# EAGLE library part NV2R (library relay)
MOTORUMPOL RELAIS 12V Ningbo Forward Relay Corporation LTD. Ningbo.Huaguan Electronics Corporation LTD. Source: http://www.dblectro.com/site/pdf/NV2R.pdf http://www2.produktinfo.conrad.com/datenblaetter/500000-524999/505013-da-01-de-Motorumpolrelais_12V.pdf Elli-Echo ER20T-S-DC12V - 20A/14VDC Conrad Nr.: 505013 - 62
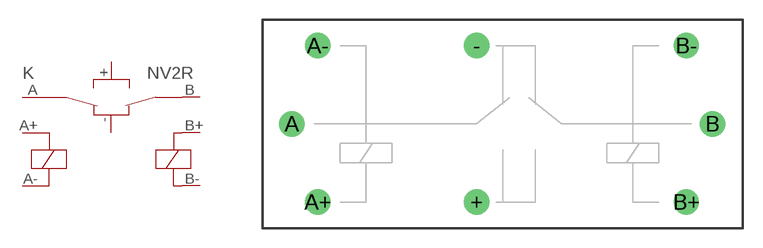
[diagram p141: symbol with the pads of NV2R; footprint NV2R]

Designator prefix K

## NV2R (OC_FARNELL: unknown; OC_NEWARK: unknown)  [NV2R]
+  +  pas
-  -  pas
A  A  pas
A+  A+  pas
A-  A-  pas
B  B  pas
B+  B+  pas
B-  B-  pas

## Footprint NV2R (pad centres in mm)
MOTORUMPOL RELAIS 12V Ningbo Forward Relay Corporation LTD. Ningbo.Huaguan Electronics Corporation LTD. Source: http://www.dblectro.com/site/pdf/NV2R.pdf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
drill 1.3 pad 1.93 round: + -2,-6; - -2,6; A -16.2,0; A+ -14.2,-6; A- -14.2,6; B 16.1,0; B+ 14.1,-6; B- 14.1,6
